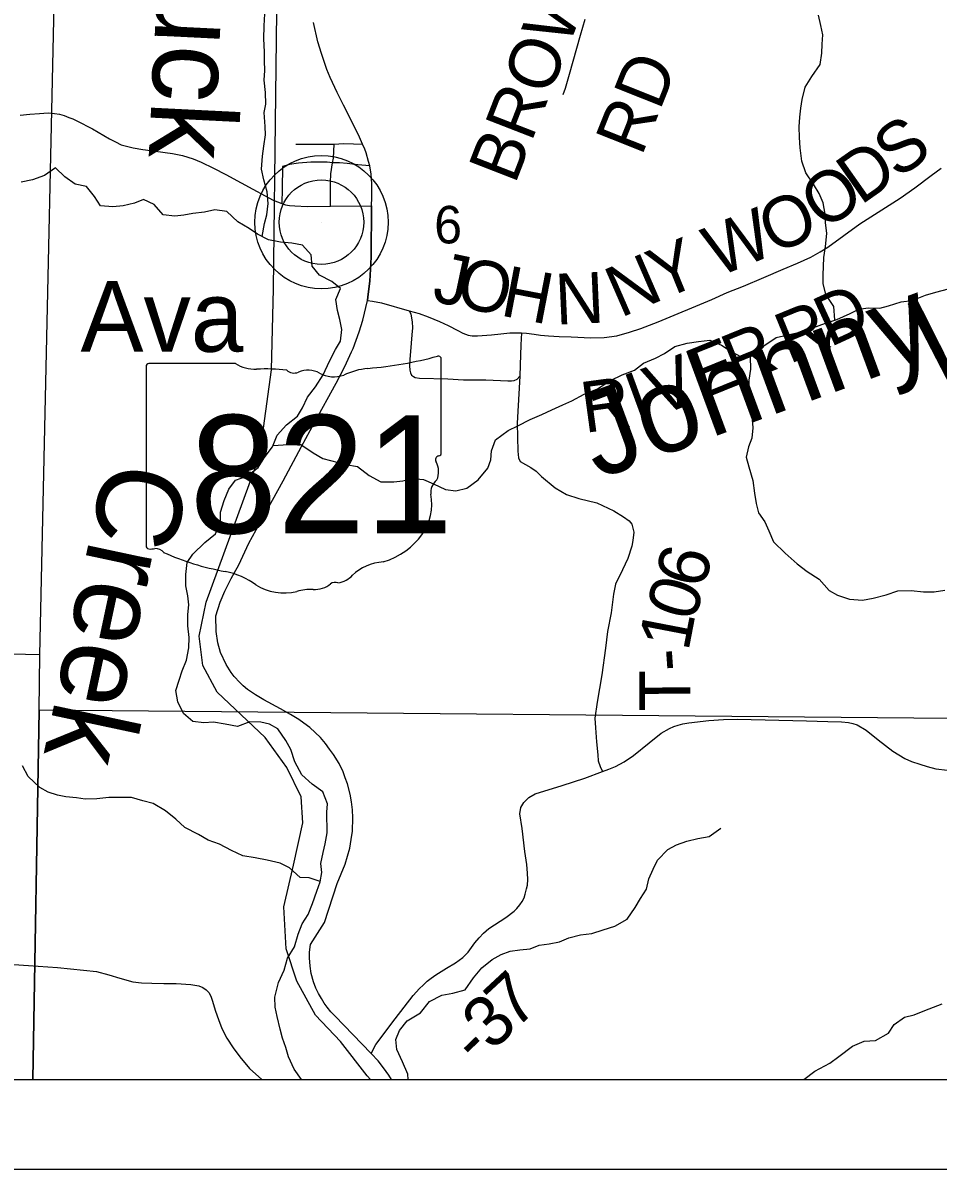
# Model space of a CAD drawing. Extents: x 0 to 34, y 0 to 22.
# Drawn here: x 5.307 to 6.329, y 14 to 15.28 of the extents above; entities that cross this region are included whole.
import ezdxf

# ---------------------------------------------------------------- set-up
doc = ezdxf.new("R2010")
doc.units = 0
for name, color, linetype in [('GM_X_Corporation', 7, 'Continuous'), ('GM_X_County_Road', 7, 'Continuous'), ('GM_X_County_Road_Text', 7, 'Continuous'), ('GM_X_Minor_River', 7, 'Continuous'), ('GM_X_Minor_River_Text', 7, 'Continuous'), ('GM_X_Rail_Line', 7, 'Continuous'), ('GM_X_Section_Text', 7, 'Continuous'), ('GM_X_State_Location', 7, 'Continuous'), ('GM_X_State_Route', 7, 'Continuous'), ('GM_X_State_Shield', 7, 'Continuous'), ('GM_X_Township_Road', 7, 'Continuous'), ('GM_X_Township_Road_Text', 7, 'Continuous'), ('GM_X_Unincorporated', 7, 'Continuous'), ('GM_X_Unincorporated_Location', 7, 'Continuous'), ('GM_X_Unincorporated_Text', 7, 'Continuous'), ('SH_Data', 7, 'Continuous')]:
    doc.layers.add(name, color=color, linetype=linetype)

msp = doc.modelspace()

# ---------------------------------------------------------------- linework, layer by layer
at = {"layer": 'GM_X_Corporation'}
for points in [[(4.3545, 15.5959), (4.3388, 15.081), (4.3354, 14.967), (4.3352, 14.9629), (4.3241, 14.5964), (4.324, 14.5949), (4.3124, 14.1), (8.9, 14.1)], [(2.1, 14.1), (8.9, 14.1)]]:
    msp.add_lwpolyline(points, dxfattribs=at)
for points in [[(5.3476, 15.5712), (6.3676, 15.5481), (6.4093, 15.5478), (6.383, 14.5028), (5.3249, 14.5126), (5.3254, 14.5744)], [(4.3084, 14.1), (5.3175, 14.1), (5.3249, 14.5126), (5.3254, 14.5744), (4.3202, 14.5977)], [(5.3175, 14.1), (6.3769, 14.1), (6.383, 14.5028), (5.3249, 14.5126)]]:
    msp.add_lwpolyline(points, close=True, dxfattribs=at)
at = {"layer": 'GM_X_County_Road'}
for points in [[(5.3034, 15.1771), (5.3143, 15.1781), (5.3251, 15.1791), (5.3349, 15.1797), (5.3417, 15.1792), (5.3476, 15.1781), (5.3525, 15.1766), (5.3578, 15.1747), (5.3623, 15.173), (5.3667, 15.171), (5.3843, 15.162), (5.4034, 15.1509), (5.41, 15.1472), (5.4165, 15.1442), (5.4224, 15.1424), (5.4298, 15.1407), (5.4405, 15.1389), (5.4547, 15.137), (5.4736, 15.1344), (5.485, 15.1321), (5.4968, 15.1284), (5.5056, 15.1246), (5.5195, 15.118), (5.5334, 15.1108), (5.5503, 15.1017), (5.5632, 15.0945), (5.5772, 15.0871), (5.5862, 15.0823), (5.5957, 15.0785), (5.5999, 15.0771), (5.6043, 15.0763), (5.6103, 15.0759), (5.624, 15.0753), (5.6502, 15.0754), (5.696, 15.0759)], [(5.6914, 14.9702), (5.6972, 14.9695), (5.7071, 14.9675), (5.738, 14.9587), (5.7493, 14.9555), (5.7592, 14.9519), (5.7717, 14.9467), (5.7817, 14.9422), (5.7923, 14.9366), (5.7979, 14.9337), (5.804, 14.9313), (5.8085, 14.9307), (5.8144, 14.9308), (5.8298, 14.9318), (5.8404, 14.9329), (5.8505, 14.9339), (5.8635, 14.9341), (5.869, 14.9335), (5.8774, 14.9325), (5.8848, 14.9316), (5.8935, 14.9308), (5.9056, 14.9301), (5.919, 14.9296), (5.9407, 14.9285), (5.9558, 14.929), (5.97, 14.9305), (5.9839, 14.9347), (5.9967, 14.939), (6.0162, 14.9462), (6.076, 14.9712), (6.0932, 14.979), (6.1112, 14.9862), (6.1341, 14.9957), (6.1556, 15.0051), (6.1715, 15.0119), (6.1867, 15.0185), (6.1969, 15.0244), (6.2054, 15.0297), (6.2414, 15.0559), (6.2865, 15.0844), (6.3027, 15.096), (6.3211, 15.1096), (6.3322, 15.1181)], [(5.696, 15.0759), (5.6955, 15.0186), (5.6941, 14.9917), (5.6918, 14.9744), (5.6914, 14.9702)], [(5.6954, 14.1291), (5.7007, 14.139), (5.7222, 14.1679), (5.7425, 14.1937), (5.7496, 14.2016), (5.7535, 14.2055), (5.758, 14.2097), (5.7626, 14.2134), (5.7678, 14.217), (5.7796, 14.2244), (5.7897, 14.2305), (5.798, 14.2365), (5.804, 14.2423), (5.8114, 14.2527), (5.8161, 14.2584), (5.821, 14.2635), (5.8268, 14.2686), (5.846, 14.281), (5.8554, 14.2881), (5.8583, 14.2911), (5.8617, 14.295), (5.8642, 14.2989), (5.8663, 14.303), (5.8677, 14.3069), (5.8691, 14.3129), (5.87, 14.3171), (5.8705, 14.3233), (5.8702, 14.3307), (5.8693, 14.3401), (5.8672, 14.3549), (5.8641, 14.3803), (5.8617, 14.3966), (5.8628, 14.404), (5.8661, 14.4095), (5.8715, 14.4152), (5.8786, 14.4193), (5.9087, 14.4284), (5.934, 14.4366), (5.9539, 14.4439), (5.9609, 14.4466), (5.9684, 14.4496), (5.9779, 14.4549), (5.9886, 14.462), (6.0061, 14.4761), (6.0193, 14.4867), (6.0287, 14.4922), (6.0334, 14.4942), (6.0383, 14.4959), (6.0437, 14.4973), (6.0504, 14.4985), (6.0725, 14.501), (6.089, 14.502), (6.1045, 14.5024), (6.1819, 14.5007), (6.2057, 14.4999), (6.2209, 14.4996), (6.2286, 14.4988), (6.2336, 14.4976), (6.2382, 14.4961), (6.2484, 14.4902), (6.2616, 14.4796), (6.2782, 14.4666), (6.2915, 14.4587), (6.2991, 14.4552), (6.3083, 14.4521), (6.3164, 14.4495), (6.3263, 14.4472), (6.3393, 14.4454)]]:
    msp.add_lwpolyline(points, dxfattribs=at)
at = {"layer": 'GM_X_Minor_River'}
for points in [[(5.5737, 15.0417), (5.5765, 15.0561), (5.5791, 15.066), (5.5805, 15.0785), (5.5794, 15.0914), (5.5755, 15.105), (5.5732, 15.1168), (5.574, 15.1312), (5.5758, 15.1425), (5.5777, 15.1551), (5.5773, 15.1645), (5.5761, 15.1801), (5.5779, 15.1896), (5.5775, 15.2025), (5.576, 15.2161), (5.5767, 15.2271), (5.5763, 15.2377), (5.5763, 15.2479), (5.5758, 15.2623), (5.5762, 15.2771), (5.5769, 15.2904)], [(6.2133, 14.9484), (6.2124, 14.9635), (6.2033, 14.9768), (6.2003, 14.9893), (6.2002, 14.9987), (6.2006, 15.0082), (6.2009, 15.0181), (6.2028, 15.0306), (6.2046, 15.045), (6.2031, 15.0571), (6.2027, 15.0666), (6.2004, 15.0791), (6.1958, 15.0897), (6.1897, 15.0999), (6.181, 15.1128), (6.1764, 15.1257), (6.1748, 15.1408), (6.174, 15.1522), (6.1736, 15.164), (6.1743, 15.175), (6.1754, 15.1848), (6.1769, 15.1947), (6.1803, 15.2083), (6.1878, 15.2205), (6.1969, 15.2338), (6.1987, 15.2463), (6.1991, 15.2566), (6.1998, 15.2668), (6.1979, 15.2774), (6.1952, 15.2888)], [(5.6347, 14.3104), (5.6385, 14.3207), (5.6404, 14.3313), (5.6392, 14.3412), (5.6418, 14.3537), (5.644, 14.3632), (5.6463, 14.3757), (5.6462, 14.3985), (5.6469, 14.4079), (5.6416, 14.4212), (5.6298, 14.4299), (5.6181, 14.4405), (5.6104, 14.4548), (5.6059, 14.4685), (5.6002, 14.4787), (5.5914, 14.4919), (5.5819, 14.4968), (5.5724, 14.4991), (5.56, 14.4994), (5.5463, 14.4944), (5.5323, 14.497), (5.5194, 14.4993), (5.5085, 14.4985), (5.4963, 14.5), (5.4861, 14.509), (5.4796, 14.5219), (5.4773, 14.5344), (5.4811, 14.5462), (5.4844, 14.5564), (5.4893, 14.5686), (5.4919, 14.5822), (5.4923, 14.5936), (5.4907, 14.6069), (5.4907, 14.6194), (5.4918, 14.6304), (5.4906, 14.6402), (5.4887, 14.6516), (5.4887, 14.6641), (5.4901, 14.6774), (5.4965, 14.6869), (5.5097, 14.6998), (5.5218, 14.7097), (5.5271, 14.7226), (5.5274, 14.7336), (5.5312, 14.7469), (5.5364, 14.7595), (5.544, 14.7693), (5.5565, 14.7739), (5.5693, 14.7838), (5.5761, 14.7945), (5.5855, 14.8066), (5.5904, 14.8196), (5.601, 14.8313), (5.6134, 14.8409), (5.6187, 14.8504), (5.6244, 14.8621), (5.6334, 14.8739), (5.6421, 14.8872), (5.6489, 14.9024), (5.6556, 14.9153), (5.6613, 14.9248), (5.6628, 14.9377), (5.6604, 14.9491), (5.6581, 14.9589), (5.6562, 14.9714), (5.6611, 14.9836), (5.6516, 14.9915), (5.638, 14.9983), (5.6296, 15.0085), (5.6284, 15.021), (5.6189, 15.032), (5.6068, 15.0342), (5.5943, 15.0353), (5.581, 15.0379), (5.5685, 15.0443), (5.5591, 15.0504), (5.5465, 15.0579), (5.5344, 15.0696), (5.5211, 15.0715), (5.5094, 15.0688), (5.4965, 15.0672), (5.4863, 15.0653), (5.4761, 15.0645), (5.4632, 15.0659), (5.4533, 15.0773), (5.4412, 15.0829), (5.4314, 15.0787), (5.4185, 15.0757), (5.4071, 15.0749), (5.3931, 15.0759), (5.3867, 15.0862), (5.3775, 15.0975), (5.365, 15.1001), (5.3533, 15.1084), (5.343, 15.1182), (5.3306, 15.1099), (5.3173, 15.1049), (5.3048, 15.1022)], [(5.5862, 14.8083), (5.6029, 14.8094), (5.6169, 14.8094), (5.6306, 14.8), (5.6416, 14.7936), (5.6674, 14.7868), (5.6803, 14.7846), (5.6932, 14.7748), (5.7064, 14.7676), (5.7208, 14.7677), (5.731, 14.7689), (5.7413, 14.7712), (5.7541, 14.7704), (5.7651, 14.7652), (5.7784, 14.7592), (5.7901, 14.7577), (5.8022, 14.7604), (5.8151, 14.7699), (5.826, 14.7828), (5.829, 14.7923), (5.8298, 14.8022), (5.8343, 14.8147), (5.8486, 14.825), (5.8592, 14.8303), (5.8732, 14.8372), (5.8861, 14.8429), (5.8974, 14.8479), (5.9095, 14.8536), (5.9197, 14.8582), (5.9333, 14.8655), (5.9484, 14.8716), (5.9628, 14.8807), (5.976, 14.8872), (5.9897, 14.8922), (5.9998, 14.9002), (6.0131, 14.9056), (6.0233, 14.9109), (6.0346, 14.9189), (6.0486, 14.9224), (6.0611, 14.9243), (6.0736, 14.9259), (6.0869, 14.9202), (6.0994, 14.9119), (6.1123, 14.9052), (6.1263, 14.9101), (6.135, 14.9204), (6.1478, 14.9288), (6.1595, 14.9315), (6.1743, 14.9349), (6.1887, 14.9395), (6.203, 14.9449), (6.2155, 14.9491), (6.2303, 14.9556), (6.2401, 14.9606), (6.2507, 14.9618), (6.2636, 14.9614), (6.2734, 14.9641), (6.2874, 14.9687), (6.2999, 14.9703), (6.3146, 14.976), (6.326, 14.9795), (6.3404, 14.9833)], [(6.1187, 14.9074), (6.1191, 14.8934), (6.1173, 14.8813), (6.1173, 14.871), (6.1192, 14.8593), (6.1204, 14.8476), (6.1212, 14.8373), (6.1216, 14.8278), (6.1205, 14.8165), (6.1171, 14.8066), (6.1145, 14.7952), (6.1172, 14.7842), (6.1218, 14.7691), (6.1237, 14.755), (6.1256, 14.7433), (6.128, 14.7331), (6.1352, 14.7229), (6.1398, 14.713), (6.1447, 14.7005), (6.158, 14.688), (6.1713, 14.676), (6.1823, 14.6673), (6.196, 14.659), (6.207, 14.6461), (6.2165, 14.6412), (6.2297, 14.6367), (6.2441, 14.6353), (6.2562, 14.6376), (6.2706, 14.6414), (6.2838, 14.646), (6.2986, 14.6461), (6.3122, 14.6446), (6.3244, 14.6446), (6.3361, 14.6466)], [(5.6386, 14.3213), (5.6264, 14.3252), (5.6161, 14.3255), (5.6044, 14.3365), (5.5938, 14.3418), (5.5794, 14.3451), (5.5661, 14.3477), (5.5521, 14.35), (5.5396, 14.356), (5.5263, 14.3628), (5.5134, 14.3673), (5.5028, 14.3737), (5.4876, 14.3816), (5.4774, 14.3907), (5.466, 14.4001), (5.4519, 14.4084), (5.4406, 14.4114), (5.4277, 14.4152), (5.4027, 14.4151), (5.3891, 14.4135), (5.3762, 14.4131), (5.3663, 14.4146), (5.3546, 14.4157), (5.3451, 14.4175), (5.3349, 14.4209), (5.3254, 14.4262), (5.3125, 14.4386), (5.306, 14.4504)], [(5.737, 14.1), (5.7365, 14.106), (5.7304, 14.1196), (5.7243, 14.1336), (5.7231, 14.1446), (5.7272, 14.1549), (5.7359, 14.1655), (5.7506, 14.1747), (5.7608, 14.1872), (5.7744, 14.1941), (5.7869, 14.1964), (5.8005, 14.2003), (5.81, 14.2136), (5.819, 14.2246), (5.8307, 14.2341), (5.8406, 14.2398), (5.8508, 14.2433), (5.8614, 14.2449), (5.8731, 14.246), (5.8833, 14.2502), (5.8943, 14.2514), (5.906, 14.2537), (5.9162, 14.2583), (5.9295, 14.2618), (5.942, 14.2633), (5.9548, 14.2672), (5.9677, 14.2714), (5.9813, 14.279), (5.9903, 14.2923), (5.9964, 14.3022), (6.0031, 14.3125), (6.0058, 14.3242), (6.0103, 14.3349), (6.0152, 14.3451), (6.0269, 14.3569), (6.0367, 14.3623), (6.048, 14.3661), (6.0605, 14.3692), (6.073, 14.3715), (6.0862, 14.3806)], [(5.6177, 14.1), (5.6096, 14.1116), (5.6031, 14.1253), (5.6001, 14.1359), (5.5966, 14.1461), (5.5939, 14.1563), (5.5905, 14.1703), (5.5882, 14.181), (5.5881, 14.192), (5.5919, 14.2083), (5.5983, 14.2223), (5.602, 14.2356), (5.6099, 14.2482), (5.6141, 14.2622), (5.6186, 14.274), (5.625, 14.2842), (5.6299, 14.2968), (5.6347, 14.3104)], [(6.1788, 14.1), (6.1912, 14.1095), (6.2078, 14.1182), (6.218, 14.1259), (6.2331, 14.1373), (6.246, 14.143), (6.2589, 14.1435), (6.2732, 14.1519), (6.2796, 14.1614), (6.2913, 14.1697), (6.3019, 14.1724), (6.3137, 14.177), (6.3333, 14.1847)]]:
    msp.add_lwpolyline(points, dxfattribs=at)
at = {"layer": 'GM_X_Rail_Line'}
msp.add_lwpolyline([(5.6946, 14.1), (5.6911, 14.1043), (5.6613, 14.1425), (5.6333, 14.1718), (5.6126, 14.21), (5.6007, 14.2459), (5.5981, 14.2929), (5.6089, 14.3396), (5.6191, 14.3868), (5.6174, 14.4158), (5.6014, 14.4484), (5.577, 14.4822), (5.5237, 14.5328), (5.5076, 14.5625), (5.5034, 14.5954), (5.5114, 14.6333), (5.5664, 14.784), (5.5752, 14.8277), (5.5843, 14.8928), (5.5863, 14.9831), (5.5917, 15.417)], dxfattribs=at)
at = {"layer": 'GM_X_State_Route'}
for points in [[(5.696, 15.0759), (5.6963, 15.0853), (5.6961, 15.1004), (5.6954, 15.1113), (5.6939, 15.1205), (5.6924, 15.1255), (5.6898, 15.1349), (5.6883, 15.139), (5.6859, 15.1448), (5.6825, 15.1527), (5.6716, 15.1746), (5.6646, 15.1882), (5.6575, 15.2025), (5.6498, 15.2191), (5.6461, 15.2283), (5.6399, 15.2459), (5.636, 15.2592), (5.6311, 15.2807)], [(5.6914, 14.9702), (5.6918, 14.9744), (5.6941, 14.9917), (5.6955, 15.0186), (5.696, 15.0759)], [(5.6737, 14.9129), (5.6754, 14.9166), (5.6822, 14.935), (5.6861, 14.9483), (5.6914, 14.9702)], [(5.7183, 14.1), (5.7152, 14.105), (5.7093, 14.1132), (5.7033, 14.1208), (5.6954, 14.1291), (5.6548, 14.1712), (5.6505, 14.1758), (5.6464, 14.181), (5.643, 14.1854), (5.6399, 14.1904), (5.6367, 14.196), (5.6336, 14.2021), (5.631, 14.2092), (5.6286, 14.2186), (5.6275, 14.2266), (5.6266, 14.236), (5.6267, 14.2424), (5.6276, 14.2507), (5.6433, 14.2755), (5.6577, 14.3188), (5.6665, 14.3407), (5.669, 14.3494), (5.6717, 14.3583), (5.6733, 14.3682), (5.6747, 14.3776), (5.6752, 14.3925), (5.6748, 14.4013), (5.6737, 14.4102), (5.6722, 14.4187), (5.6692, 14.4303), (5.6666, 14.4369), (5.6641, 14.4436), (5.6597, 14.4529), (5.6535, 14.4631), (5.6491, 14.4692), (5.6444, 14.4755), (5.6388, 14.482), (5.633, 14.4878), (5.6269, 14.4931), (5.6204, 14.4981), (5.6147, 14.502), (5.6054, 14.5078), (5.5942, 14.5141), (5.5758, 14.5243), (5.5665, 14.5296), (5.5575, 14.5357), (5.5527, 14.5398), (5.5488, 14.5436), (5.5427, 14.5503), (5.5392, 14.5548), (5.5335, 14.5637), (5.5272, 14.5769), (5.5243, 14.5879), (5.5223, 14.6005), (5.5222, 14.6178), (5.5268, 14.6333), (5.5321, 14.6455), (5.5393, 14.6595), (5.5478, 14.6749), (5.5589, 14.699), (5.5795, 14.7363), (5.5971, 14.7686), (5.6179, 14.8071), (5.6322, 14.8338), (5.6566, 14.8778), (5.6661, 14.8964), (5.6737, 14.9129)]]:
    msp.add_lwpolyline(points, dxfattribs=at)
at = {"layer": 'GM_X_State_Shield'}
for p, q in [((5.7738, 14.7999), (5.7738, 14.9046)), ((5.4442, 14.8962), (5.4442, 14.6961)), ((5.5439, 14.8997), (5.4474, 14.8997)), ((5.7737, 14.8), (5.7738, 14.7999))]:
    msp.add_line(p, q, dxfattribs=at)
for centre, major_axis, start_param, end_param in [((5.6564, 15.1725), (0.3495, 0), 4.814394, 5.042369), ((5.7701, 14.9051), (0.00367, 0), 6.141152, 7.989035), ((5.4479, 14.8967), (0.00382, 0), 1.712693, 3.28349), ((5.5669, 14.9229), (0.037, 0), 4.042523, 4.731795), ((5.5792, 14.7873), (0.133, 0), 1.404758, 1.657858), ((5.6094, 14.8977), (0.0107, 0), 3.836095, 5.185415), ((5.6251, 14.8746), (0.0222, 0), 0.950623, 2.079405), ((5.6537, 14.9063), (0.0267, 0), 4.081561, 5.145723), ((5.7009, 14.8385), (0.0703, 0), 1.699011, 2.107814), ((5.7698, 14.7995), (0.00393, 0), 5.05454, 6.418171), ((5.7729, 14.7923), (0.00568, 0), 1.883978, 3.671073), ((5.7368, 14.779), (0.0341, 0), 5.934695, 6.695948), ((5.7869, 14.7561), (0.0248, 0), 2.387724, 3.262537), ((5.6759, 14.7428), (0.0874, 0), 5.101752, 6.440018), ((5.448, 14.6957), (0.00385, 0), 3.00124, 4.508301), ((5.4486, 14.7161), (0.0294, 0), 4.665946, 4.897461), ((5.4546, 14.6846), (0.0106, 0), 0.519207, 1.627899), ((5.5884, 14.8644), (0.2524, 0), 4.195997, 4.488961), ((5.7128, 14.6399), (0.0479, 0), 1.647645, 2.488434), ((5.5132, 14.6062), (0.079, 0), 0.823519, 1.323587), ((5.6521, 14.6767), (0.0282, 0), 4.937069, 5.64225), ((5.5986, 14.6836), (0.0501, 0), 4.026481, 4.996735), ((5.6275, 14.6144), (0.0412, 0), 1.495662, 1.94098), ((5.6312, 14.6686), (0.0267, 0), 4.691044, 5.507374), ((5.6553, 14.6492), (0.00752, 0), 1.147584, 2.315152)]:
    msp.add_ellipse(centre, major_axis=major_axis, ratio=0.8, start_param=start_param, end_param=end_param, dxfattribs=at)
at = {"layer": 'GM_X_Township_Road'}
for points in [[(5.9343, 15.2839), (5.9289, 15.2662), (5.9165, 15.2224), (5.9121, 15.207), (5.9097, 15.1998)], [(5.6114, 15.1449), (5.6541, 15.1447), (5.6647, 15.1454), (5.6758, 15.1451), (5.6859, 15.1448)], [(5.6524, 15.1238), (5.6533, 15.1293), (5.6541, 15.1447)], [(5.6939, 15.1205), (5.6808, 15.1217), (5.6688, 15.1231), (5.6602, 15.1239), (5.6524, 15.1238), (5.6463, 15.1246), (5.6403, 15.1248), (5.6282, 15.1246), (5.6142, 15.1236), (5.6043, 15.122), (5.5965, 15.1199), (5.5961, 15.0949), (5.5957, 15.0785)], [(5.6502, 15.0754), (5.6501, 15.1018), (5.6504, 15.1117), (5.6524, 15.1238)], [(5.738, 14.9587), (5.7397, 14.9551), (5.7405, 14.9506), (5.7414, 14.9462), (5.7417, 14.9396), (5.7409, 14.9318), (5.7396, 14.9131), (5.7387, 14.9048), (5.7385, 14.897), (5.7387, 14.8925), (5.7393, 14.8894), (5.7407, 14.8869), (5.7427, 14.8852), (5.7446, 14.8842), (5.7494, 14.8834), (5.7812, 14.8825), (5.7988, 14.8816), (5.8237, 14.8816), (5.8481, 14.8804), (5.8523, 14.8806), (5.8554, 14.8809), (5.8584, 14.8822), (5.8615, 14.8856)], [(5.8635, 14.9341), (5.8627, 14.9205), (5.8618, 14.8979), (5.8615, 14.8856)], [(5.8615, 14.8856), (5.8587, 14.8331), (5.8593, 14.802), (5.86, 14.7944), (5.8619, 14.7905), (5.8738, 14.7836), (5.8798, 14.7795), (5.8857, 14.7735), (5.9012, 14.7609), (5.9138, 14.7535), (5.9275, 14.7491), (5.9476, 14.744), (5.9664, 14.7351), (5.9774, 14.7286), (5.9836, 14.7241), (5.9866, 14.7203), (5.9888, 14.7115), (5.9879, 14.7019), (5.9868, 14.6959), (5.9822, 14.6819), (5.9763, 14.6695), (5.9685, 14.6534), (5.9662, 14.6421), (5.9634, 14.6214), (5.9595, 14.6006), (5.9572, 14.5817), (5.9531, 14.5521), (5.948, 14.5216), (5.9453, 14.5036), (5.946, 14.4928), (5.9473, 14.4773), (5.9486, 14.4627), (5.9492, 14.4559), (5.9514, 14.4497), (5.9539, 14.4439)], [(5.2741, 14.2299), (5.3128, 14.2272), (5.3451, 14.2252), (5.3889, 14.2206), (5.4026, 14.2168), (5.415, 14.2131), (5.4294, 14.2093), (5.4391, 14.2081), (5.4504, 14.2075), (5.4639, 14.2072), (5.4779, 14.2071), (5.4941, 14.2063), (5.5031, 14.2047), (5.5077, 14.2029), (5.5114, 14.2001), (5.5141, 14.1971), (5.5165, 14.1932), (5.5183, 14.1874), (5.5212, 14.1775), (5.5254, 14.1659), (5.5283, 14.1583), (5.5315, 14.1517), (5.5345, 14.1463), (5.5415, 14.1355), (5.5488, 14.1252), (5.5597, 14.1124), (5.5734, 14.1)]]:
    msp.add_lwpolyline(points, dxfattribs=at)
at = {"layer": 'GM_X_Unincorporated'}
for radius in [0.0744, 0.0472]:
    msp.add_circle((5.64, 15.0576), radius, dxfattribs=at)
at = {"layer": 'GM_X_Unincorporated_Location'}
msp.add_line((5.64, 15.0576), (5.64, 15.0576), dxfattribs=at)
at = {"layer": 'SH_Data'}
for p, q in [((2.1, 14.1), (8.9, 14.1)), ((2, 14), (9, 14))]:
    msp.add_line(p, q, dxfattribs=at)

# ---------------------------------------------------------------- texts
at = {"layer": 'GM_X_County_Road_Text'}
for s, rotation, p in [('S', 35.6309, (6.2834, 15.105)), ('D', 35.1168, (6.2421, 15.0759)), ('O', 35.1809, (6.2012, 15.0471)), ('O', 23.4151, (6.1443, 15.021)), ('W', 22.1214, (6.082, 14.9957)), ('Y', 22.1099, (6.0194, 14.9703)), ('J', 347.9868, (5.7622, 14.9698)), ('O', 348.003, (5.7883, 14.9643)), ('N', 23.5158, (5.9739, 14.9504)), ('H', 349.0764, (5.8384, 14.9537)), ('N', 2.5611, (5.902, 14.9431)), ('D', 24.6667, (6.2077, 14.9175)), ('R', 22.2574, (6.1622, 14.8988)), ('R', 22.0829, (6.1025, 14.8746)), ('E', 22.0401, (6.0631, 14.8586)), ('V', 21.4418, (6.016, 14.8401)), ('I', 20.1172, (5.9927, 14.8316)), ('R', 7.7713, (5.9338, 14.8221)), ('7', 42.9021, (5.8559, 14.1547)), ('3', 43.5721, (5.8307, 14.1307)), ('-', 43.9788, (5.814, 14.1146))]:
    msp.add_text(s, height=0.0568, rotation=rotation, dxfattribs=at).set_placement(p)
at = {"layer": 'GM_X_Minor_River_Text'}
for s, height, rotation, p in [('Duck', 0.0947, 267.1501, (5.4614, 15.419)), ('Woods', 0.09469, 12.212, (6.3139, 14.874)), ('Johnny', 0.09469, 20.2643, (5.9484, 14.7699)), ('Creek', 0.09471, 257.9571, (5.4003, 14.7946))]:
    msp.add_text(s, height=height, rotation=rotation, dxfattribs=at).set_placement(p)
at = {"layer": 'GM_X_Section_Text'}
msp.add_text('6', height=0.0419, rotation=0, dxfattribs=at).set_placement((5.7659, 15.0339))
at = {"layer": 'GM_X_State_Location'}
for s in ['s', 'r']:
    msp.add_text(s, height=0.000189, dxfattribs=at).set_placement((5.6053, 14.7829))
msp.add_text('821', height=0.000189, rotation=0, dxfattribs=at).set_placement((5.5384, 14.7691))
at = {"layer": 'GM_X_State_Shield'}
msp.add_text('821', height=0.13184, dxfattribs=at).set_placement((5.4927, 14.7102))
at = {"layer": 'GM_X_Township_Road_Text'}
for s, height, rotation, p in [('BROWN', 0.05682, 68.739, (5.856, 15.0988)), ('RD', 0.05682, 68.289, (5.9975, 15.1302)), ('6', 0.0568, 76.0522, (6.0672, 14.6468)), ('0', 0.0568, 72.8636, (6.0559, 14.61)), ('1', 0.0568, 79.0993, (6.0497, 14.5772)), ('-', 0.0568, 94.0121, (6.0516, 14.5578)), ('T', 0.0568, 90.3857, (6.052, 14.5114))]:
    msp.add_text(s, height=height, rotation=rotation, dxfattribs=at).set_placement(p)
at = {"layer": 'GM_X_Unincorporated_Text'}
msp.add_text('Ava', height=0.07898, rotation=0, dxfattribs=at).set_placement((5.3709, 14.9129))

doc.saveas('drawing.dxf')
